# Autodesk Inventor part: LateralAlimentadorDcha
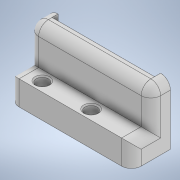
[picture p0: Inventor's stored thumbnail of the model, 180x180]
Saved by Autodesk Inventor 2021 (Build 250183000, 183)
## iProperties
Created: 2021-02
Part Number: LateralAlimentadorDcha
Material: Genérico
Document SubType Name: Modeling
Designer: ATOUZA
Density: 1 g/cm^3
Appearance: Valor por defecto
Author: ATOUZA
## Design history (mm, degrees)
node "Plano de trabajo1"
sketch "Boceto1"
  geometry: L1 (25, 26)-(-25, 26); L2 (-25, 26)-(-25, 18); L3 (-25, 18)-(-21, 18); L4 (-21, 18)-(-21, 20.5); L5 (25, 26)-(25, 18); L6 (25, 18)-(21, 18); L7 (21, 18)-(21, 20.5); L8 (25, 26)-(-25, 26); L9 (-21, 20.5)-(21, 20.5); 1 further point
  constraints: 18 end point, 3 parallel, 2 horizontal, 2 perpendicular, 1 point on line
  dimensions: "d1" = 4 distance of L3.end L2.end; "d2" = 4 distance of L5.end L6.end; "d3" = 8 distance of L1.start L5.end; "d4" = 50 distance of L1.start L1.end; "d38" = 42 distance of L4.end L7.end; "d39" = 2.5 distance of L6.end L7.end
extrude "Extrusión2" new body sketch "Boceto1" distance "d17" = 25; taper "d18" = 0 deg
sketch "Boceto4"
  geometry: L1 (-25, 26)-(25, 26) reference; L2 (25, 26)-(-25, 26); L3 (-25, 26)-(-25, 34); L4 (-25, 34)-(25, 34); L5 (25, 34)-(25, 26); L6 (-21, 18)-(-21, 20.5) reference; L7 (-21, 20.5)-(19, 20.5); L8 (19, 20.5)-(19, -19.5); L9 (19, -19.5)-(-21, -19.5); L10 (-21, -19.5)-(-21, 20.5); L11 (0, 0)-(0, 30); L12 (0, 30)-(-25, 30); L13 (0, 30)-(25, 30); C1 r 2 at (-12.5, 30); C2 r 2 at (12.5, 30); 1 further point
  constraints: 22 end point, 4 midpoint, 4 parallel, 2 centre point, 2 horizontal, 2 perpendicular, 1 vertical
  dimensions: "d19" = 8 distance of L2.end L3.end; "d22" = 40 distance of L8.end L9.end; "d23" = 40 distance of L7.end L8.end; "d26" = 30 distance of L11.start L11.end; "d27" = 4 diameter of C1; "d28" = 4 diameter of C2
extrude "Extrusión3" join sketch "Boceto4" distance "d20" = 10; taper "d21" = 0 deg
sketch "Boceto5"
  geometry: L1 (-25, -34)-(25, -34) reference; L2 (-25, -26)-(25, -26) reference; L3 (0, -30)-(-31, -30); L4 (0, -30)-(25, -30); L5 (25, -18)-(25, -34) reference; L6 (4.811, 50.86)-(5.011, 50.86) reference; L7 (-15.5, 429.14)-(-15.5, -50.86) reference; L8 (4.5, 429.14)-(4.5, -50.86) reference; 3 further points
  constraints: 4 end point, 4 point on line, 1 horizontal, 1 midpoint
hole "Agujero2" sketch "Boceto5" diameter "d29" = 5; stored, may be unused: countersink angle "d33" = 90 deg, drill point angle "d35" = 118 deg; dims "d30" = 6, "d31" = 6, "d32" = 2, "d34" = 8
fillet "Empalme1" dims "d37" = 4
node "Sólido2"
node "Referencia3"
node "Referencia4"
node "Referencia5"
